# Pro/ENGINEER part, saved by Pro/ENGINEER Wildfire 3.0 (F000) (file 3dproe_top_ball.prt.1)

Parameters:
  DESCRIPTION = "COMPRESSION RING - 6"
  MODELED_BY = "L. CONARD"
  PTC_COMMON_NAME = "COMPRESSION RING - 6"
